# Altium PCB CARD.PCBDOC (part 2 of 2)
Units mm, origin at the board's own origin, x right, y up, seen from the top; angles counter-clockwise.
Board outline 129.79 x 109.73 mm, 2 copper layers (Top Layer, Bottom Layer); 204 components, 30 nets, 765 pads, 348 vias.
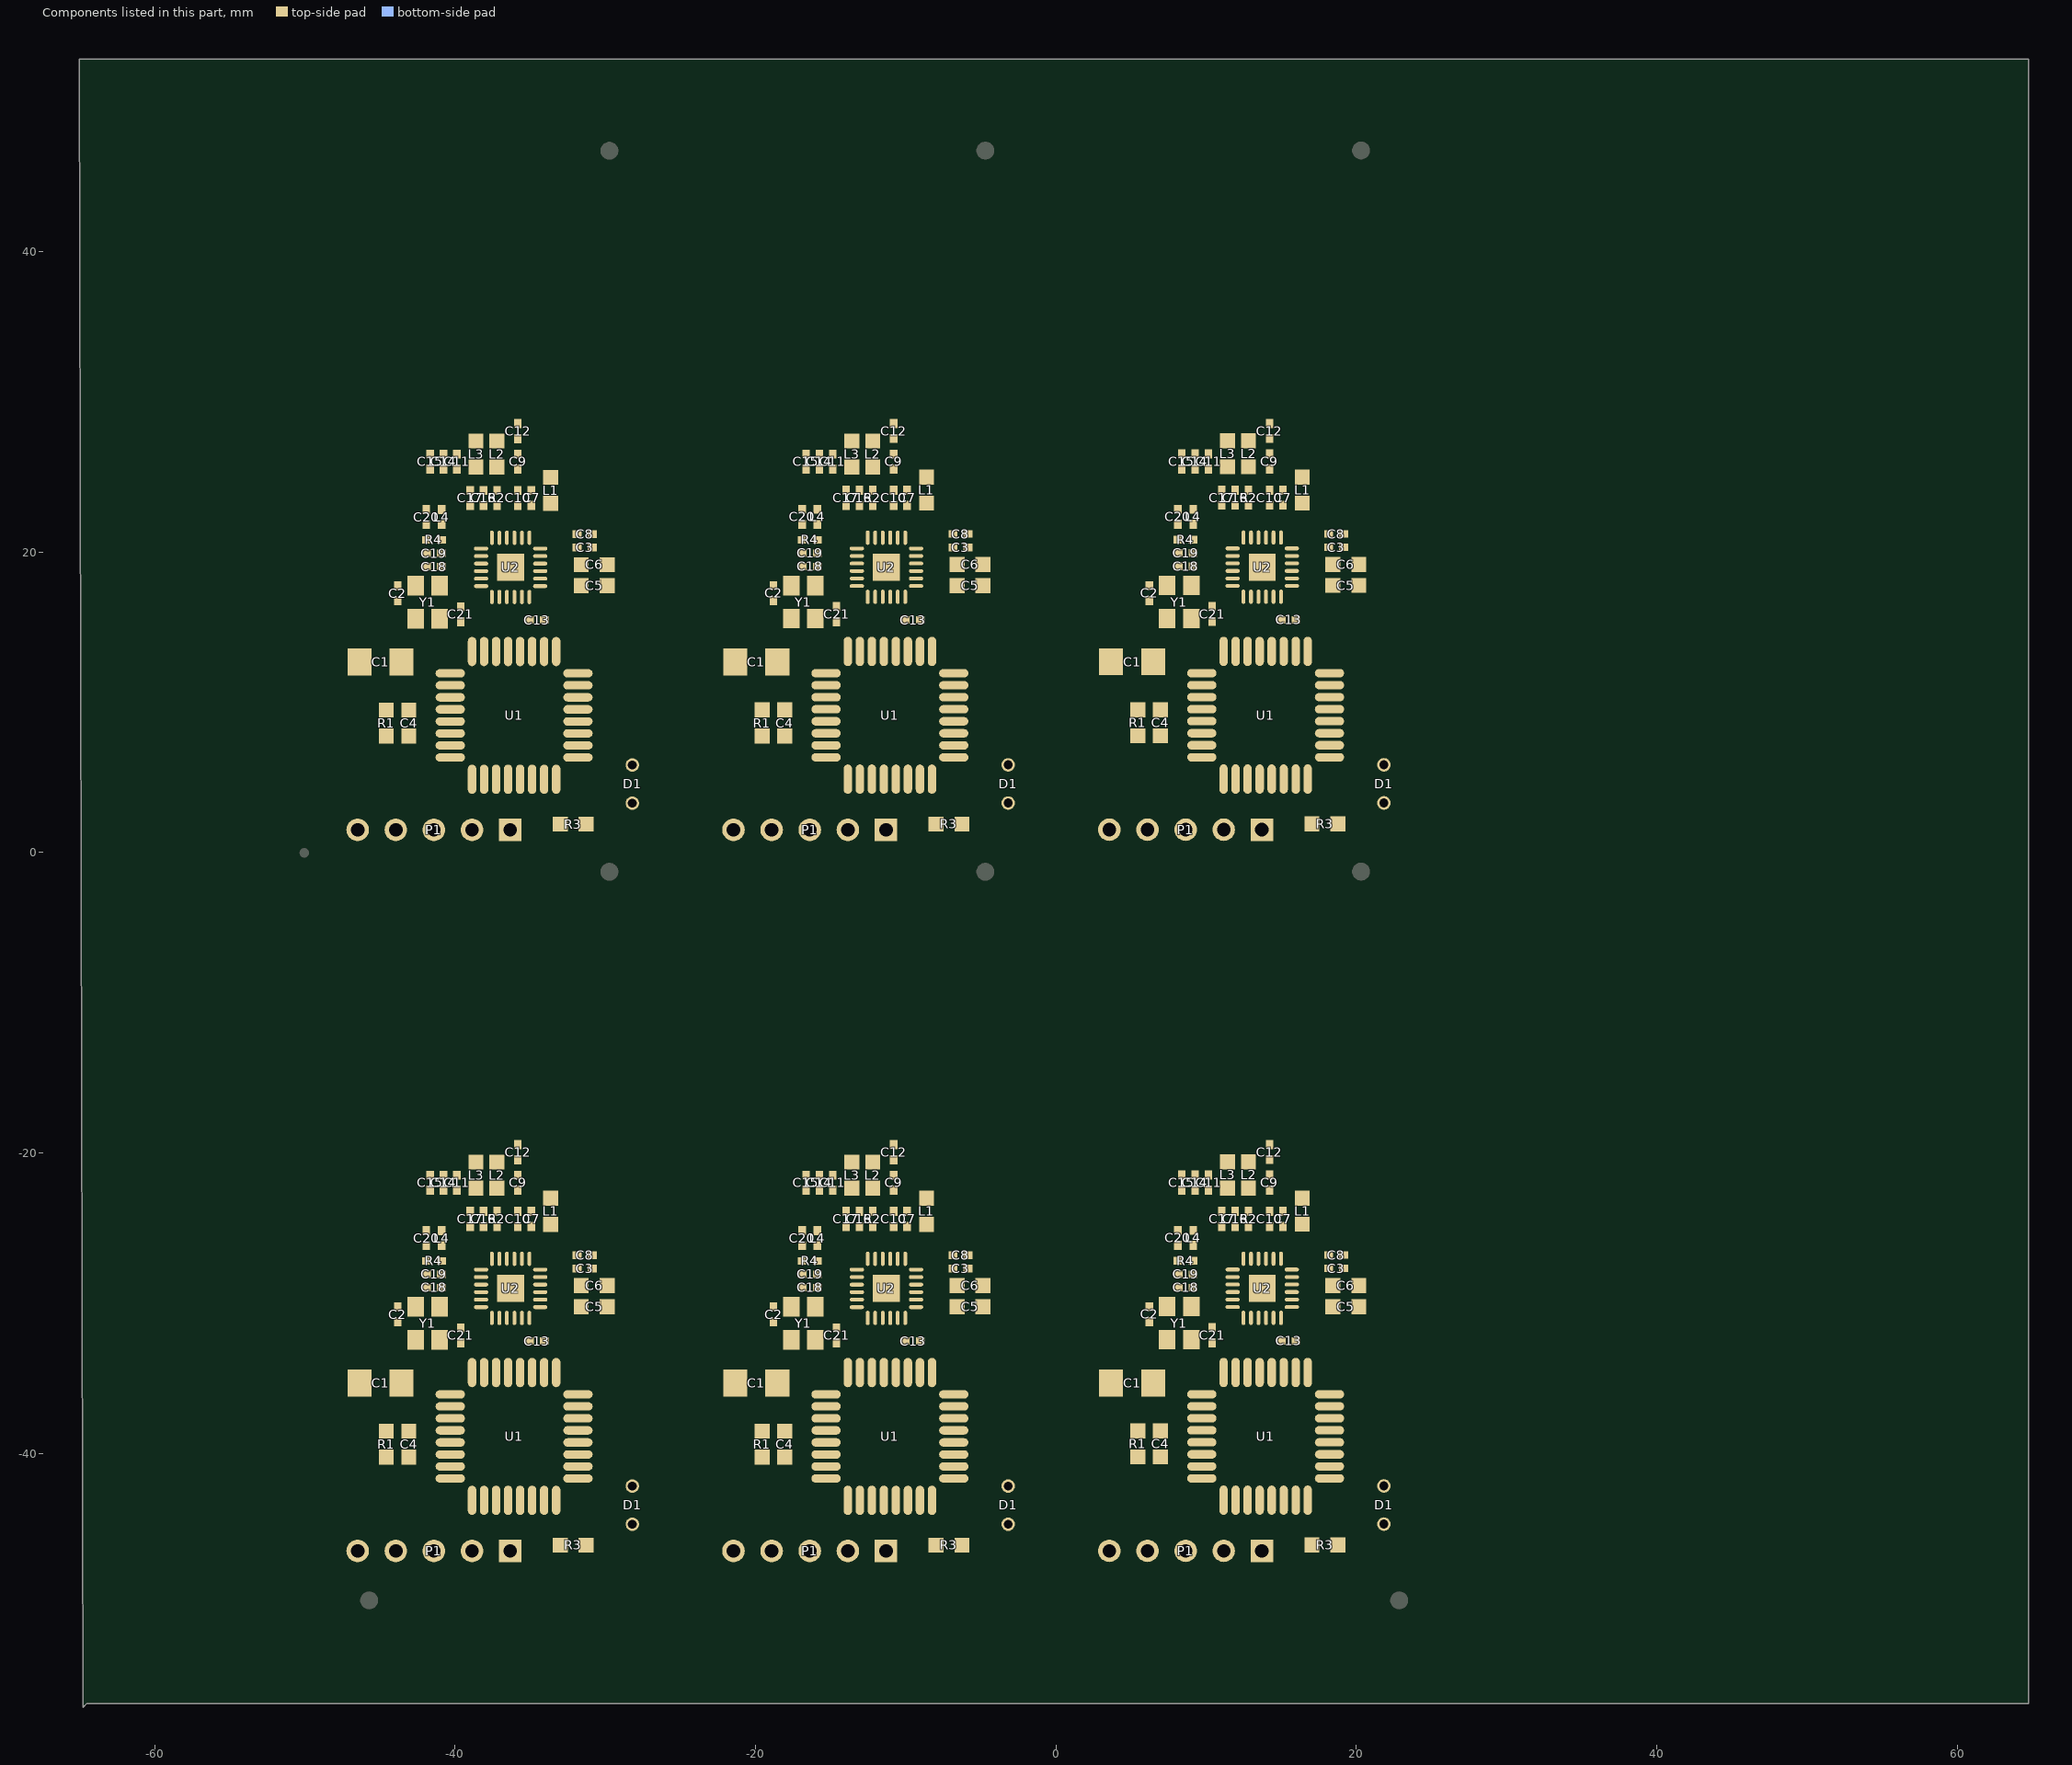
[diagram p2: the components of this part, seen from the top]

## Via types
v1: diameter 0.457, hole 0.381, Top Layer to Bottom Layer, 228 vias
v2: diameter 0.508, hole 0.305, Top Layer to Bottom Layer, 30 vias
v3: diameter 0.508, hole 0.254, Top Layer to Bottom Layer, tented top, 30 vias
v4: diameter 0.559, hole 0.356, Top Layer to Bottom Layer, 18 vias
v5: diameter 0.533, hole 0.279, Top Layer to Bottom Layer, 18 vias
v6: diameter 0.762, hole 0.457, Top Layer to Bottom Layer, 12 vias
v7: diameter 0.61, hole 0.356, Top Layer to Bottom Layer, 6 vias
v8: diameter 0.635, hole 0.381, Top Layer to Bottom Layer, 6 vias

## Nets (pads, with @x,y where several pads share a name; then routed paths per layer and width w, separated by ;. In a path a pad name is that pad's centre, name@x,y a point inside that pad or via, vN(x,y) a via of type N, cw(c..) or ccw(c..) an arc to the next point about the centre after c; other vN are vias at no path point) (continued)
copper on no net: | length 1969.2
  Top Layer w0.203: -43.942,-46.615 -43.028,-45.701 -43.028,-40.24 ; -43.942,1.385 -43.028,2.299 -43.028,7.76 ; -42.977,-44.837 -36.043,-44.837 -35.662,-44.456 -35.662,-43.745 ; -42.977,3.163 -36.043,3.163 -35.662,3.544 -35.662,4.255 ; -42.316,-30.715 -41.758,-31.273 -40.284,-31.273 -38.786,-29.775 -38.252,-29.775 ; -42.316,17.285 -41.758,16.727 -40.284,16.727 -38.786,18.225 -38.252,18.225 ; -40.894,-28.073 -40.767,-28.2 -40.386,-28.2 -39.827,-28.759 -38.456,-28.759 ; -40.894,19.927 -40.767,19.8 -40.386,19.8 -39.827,19.241 -38.456,19.241 ; -40.869,-26.27 -40.259,-26.27 cw(c-40.259,-26.676) -39.853,-26.676 -39.853,-27.895 ccw(c-39.497,-27.895) -39.497,-28.251 ; -40.869,21.73 -40.259,21.73 cw(c-40.259,21.324) -39.853,21.324 -39.853,20.105 ccw(c-39.497,20.105) -39.497,19.749 ; -40.767,-32.62 -38.608,-32.62 -38.456,-32.467 -38.456,-30.263 ; -40.767,15.38 -38.608,15.38 -38.456,15.533 -38.456,17.737 ; -40.742,-29.013 -40.361,-29.013 -40.107,-29.267 -38.075,-29.267 ; -40.742,18.987 -40.361,18.987 -40.107,18.733 -38.075,18.733 ; -40.691,-25.33 -39.903,-25.33 ; -40.691,22.67 -39.903,22.67 ; -40.081,-36.125 -39.091,-36.125 -38.608,-36.607 v2(-38.608,-41.484) ; -40.081,11.875 -39.091,11.875 -38.608,11.393 v2(-38.608,6.516) ; -39.929,-25.33 cw(c-39.929,-25.863) -39.395,-25.863 ; -39.929,22.67 cw(c-39.929,22.137) -39.395,22.137 ; -39.522,-28.251 -38.456,-28.251 ; -39.522,19.749 -38.456,19.749 ; -39.395,-25.838 -39.395,-27.387 ccw(c-39.014,-27.387) -39.014,-27.768 -38.303,-27.768 ; -39.395,22.162 -39.395,20.613 ccw(c-39.014,20.613) -39.014,20.232 -38.303,20.232 ; -38.76,-34.626 -38.76,-35.718 -37.973,-36.506 v2@-37.973,-41.154 ; -38.76,13.374 -38.76,12.282 -37.973,11.494 v2@-37.973,6.846 ; -37.998,-34.601 -37.998,-35.718 -37.338,-36.379 v2(-37.338,-40.9) ; -37.998,13.399 -37.998,12.282 -37.338,11.621 v2(-37.338,7.1) ; -37.965,-23.89 -37.236,-23.89 ; -37.965,24.11 -37.236,24.11 ; -37.268,-34.618 -37.268,-33.007 -37.059,-32.797 -37.059,-31.019 ; -37.268,13.382 -37.268,14.993 -37.059,15.203 -37.059,16.981 ; -37.211,-24.974 -37.211,-25.66 -37.059,-25.812 -37.059,-26.905 ; -37.211,-20.682 -37.211,-19.769 cw(c-36.777,-19.769) -37.084,-19.462 ; -37.211,23.026 -37.211,22.34 -37.059,22.188 -37.059,21.095 ; -37.211,27.318 -37.211,28.231 cw(c-36.777,28.231) -37.084,28.538 ; -37.059,-19.437 cw(c-36.767,-19.729) -36.767,-19.316 -35.973,-19.316 ; -37.059,28.563 cw(c-36.767,28.271) -36.767,28.684 -35.973,28.684 ; -36.957,-22.587 -36.551,-22.993 -36.551,-26.955 ; -36.957,25.413 -36.551,25.007 -36.551,21.045 ; -36.551,-34.067 -36.551,-31.146 ; -36.551,-27.108 -36.55,-27.043 -36.551,-27.082 ; -36.551,13.933 -36.551,16.854 ; -36.551,20.892 -36.55,20.957 -36.551,20.918 ; -36.047,-27.043 -36.047,-25.766 -35.814,-25.533 -35.814,-24.89 ; -36.047,20.957 -36.047,22.234 -35.814,22.467 -35.814,23.11 ; -36.043,-30.983 -36.043,-30.969 ; -36.043,-30.892 -36.043,-32.797 -35.662,-33.178 -35.662,-34.321 ; -36.043,17.017 -36.043,17.031 ; -36.043,17.108 -36.043,15.203 -35.662,14.822 -35.662,13.679 ; -35.839,-20.529 -35.814,-20.524 -35.798,-20.521 ; -35.839,27.471 -35.814,27.476 -35.798,27.479 ; -35.547,-30.983 -35.047,-30.983 -35.047,-32.338 ; -35.547,17.017 -35.047,17.017 -35.047,15.662 ; -35.047,-27.043 -35.047,-25.012 ; -35.047,20.957 -35.047,22.988 ; -34.442,-28.276 -33.426,-28.276 -32.918,-27.768 -32.004,-27.768 ; -34.442,19.724 -33.426,19.724 -32.918,20.232 -32.004,20.232 ; -34.327,-29.763 -33.362,-29.763 -33.198,-29.927 v2@-33.198,-31.197 ; -34.327,-27.763 -33.573,-27.763 -32.664,-26.854 -31.902,-26.854 ; -34.327,18.237 -33.362,18.237 -33.198,18.073 v2@-33.198,16.803 ; -34.327,20.237 -33.573,20.237 -32.664,21.146 -31.902,21.146 ; -34.087,-30.308 -34.087,-31.35 -33.655,-31.781 -32.614,-31.781 -29.769,-34.626 -29.769,-41.408 -30.023,-41.662 -31.217,-41.662 ; -34.087,17.692 -34.087,16.65 -33.655,16.219 -32.614,16.219 -29.769,13.374 -29.769,6.592 -30.023,6.338 -31.217,6.338 ; -33.198,-34.112 v2(-33.198,-32.366) ; -33.198,13.888 v2(-33.198,15.634) ; -18.923,-46.615 -18.009,-45.701 -18.009,-40.24 ; -18.923,1.391 -18.009,2.305 -18.009,7.766 ; -17.958,-44.837 -11.024,-44.837 -10.643,-44.456 -10.643,-43.745 ; -17.958,3.169 -11.024,3.169 -10.643,3.55 -10.643,4.261 ; -17.297,-30.715 -16.739,-31.273 -15.265,-31.273 -13.767,-29.775 -13.233,-29.775 ; -17.297,17.291 -16.739,16.733 -15.265,16.733 -13.767,18.231 -13.233,18.231 ; -15.875,-28.073 -15.748,-28.2 -15.367,-28.2 -14.808,-28.759 -13.437,-28.759 ; -15.875,19.933 -15.748,19.806 -15.367,19.806 -14.808,19.247 -13.437,19.247 ; -15.85,-26.27 -15.24,-26.27 cw(c-15.24,-26.676) -14.834,-26.676 -14.834,-27.895 ccw(c-14.478,-27.895) -14.478,-28.251 ; -15.85,21.736 -15.24,21.736 cw(c-15.24,21.33) -14.834,21.33 -14.834,20.111 ccw(c-14.478,20.111) -14.478,19.755 ; -15.748,-32.62 -13.589,-32.62 -13.437,-32.467 -13.437,-30.263 ; -15.748,15.386 -13.589,15.386 -13.437,15.539 -13.437,17.743 ; -15.723,-29.013 -15.342,-29.013 -15.088,-29.267 -13.056,-29.267 ; -15.723,18.993 -15.342,18.993 -15.088,18.739 -13.056,18.739 ; -15.672,-25.33 -14.884,-25.33 ; -15.672,22.676 -14.884,22.676 ; -15.062,-36.125 -14.072,-36.125 -13.589,-36.607 v2(-13.589,-41.484) ; -15.062,11.881 -14.072,11.881 -13.589,11.399 v2(-13.589,6.522) ; -14.91,-25.33 cw(c-14.91,-25.863) -14.376,-25.863 ; -14.91,22.676 cw(c-14.91,22.143) -14.376,22.143 ; -14.503,-28.251 -13.437,-28.251 ; -14.503,19.755 -13.437,19.755 ; -14.376,-25.838 -14.376,-27.387 ccw(c-13.995,-27.387) -13.995,-27.768 -13.284,-27.768 ; -14.376,22.168 -14.376,20.619 ccw(c-13.995,20.619) -13.995,20.238 -13.284,20.238 ; -13.741,-34.626 -13.741,-35.718 -12.954,-36.506 v2@-12.954,-41.154 ; -13.741,13.38 -13.741,12.288 -12.954,11.5 v2@-12.954,6.852 ; -12.979,-34.601 -12.979,-35.718 -12.319,-36.379 v2(-12.319,-40.9) ; -12.979,13.405 -12.979,12.288 -12.319,11.627 v2(-12.319,7.106) ; -12.946,-23.89 -12.217,-23.89 ; -12.946,24.116 -12.217,24.116 ; -12.249,-34.618 -12.249,-33.007 -12.04,-32.797 -12.04,-31.019 ; -12.249,13.388 -12.249,14.999 -12.04,15.209 -12.04,16.987 ; -12.192,-24.974 -12.192,-25.66 -12.04,-25.812 -12.04,-26.905 ; -12.192,-20.682 -12.192,-19.769 cw(c-11.758,-19.769) -12.065,-19.462 ; -12.192,23.032 -12.192,22.346 -12.04,22.194 -12.04,21.101 ; -12.192,27.324 -12.192,28.237 cw(c-11.758,28.237) -12.065,28.544 ; -12.04,-19.437 cw(c-11.748,-19.729) -11.748,-19.316 -10.954,-19.316 ; -12.04,28.569 cw(c-11.748,28.277) -11.748,28.69 -10.954,28.69 ; -11.938,-22.587 -11.532,-22.993 -11.532,-26.955 ; -11.938,25.419 -11.532,25.013 -11.532,21.051 ; -11.532,-34.067 -11.532,-31.146 ; -11.532,-27.108 -11.531,-27.043 -11.532,-27.082 ; -11.532,13.939 -11.532,16.86 ; -11.532,20.898 -11.531,20.963 -11.532,20.924 ; -11.028,-27.043 -11.028,-25.766 -10.795,-25.533 -10.795,-24.89 ; -11.028,20.963 -11.028,22.24 -10.795,22.473 -10.795,23.116 ; -11.024,-30.983 -11.024,-30.969 ; -11.024,-30.892 -11.024,-32.797 -10.643,-33.178 -10.643,-34.321 ; -11.024,17.023 -11.024,17.037 ; -11.024,17.114 -11.024,15.209 -10.643,14.828 -10.643,13.685 ; -10.82,-20.529 -10.795,-20.524 -10.779,-20.521 ; -10.82,27.477 -10.795,27.482 -10.779,27.485 ; -10.528,-30.983 -10.028,-30.983 -10.028,-32.338 ; -10.528,17.023 -10.028,17.023 -10.028,15.668 ; -10.028,-27.043 -10.028,-25.012 ; -10.028,20.963 -10.028,22.994 ; -9.423,-28.276 -8.407,-28.276 -7.899,-27.768 -6.985,-27.768 ; -9.423,19.73 -8.407,19.73 -7.899,20.238 -6.985,20.238 ; -9.308,-29.763 -8.343,-29.763 -8.179,-29.927 v2@-8.179,-31.197 ; -9.308,-27.763 -8.554,-27.763 -7.645,-26.854 -6.883,-26.854 ; -9.308,18.243 -8.343,18.243 -8.179,18.079 v2@-8.179,16.809 ; -9.308,20.243 -8.554,20.243 -7.645,21.152 -6.883,21.152 ; -9.068,-30.308 -9.068,-31.35 -8.636,-31.781 -7.595,-31.781 -4.75,-34.626 -4.75,-41.408 -5.004,-41.662 -6.198,-41.662 ; -9.068,17.698 -9.068,16.656 -8.636,16.225 -7.595,16.225 -4.75,13.38 -4.75,6.598 -5.004,6.344 -6.198,6.344 ; -8.179,-34.112 v2(-8.179,-32.366) ; -8.179,13.894 v2(-8.179,15.64) ; 6.096,-46.609 7.01,-45.695 7.01,-40.234 ; 7.061,-44.831 13.995,-44.831 14.376,-44.45 14.376,-43.739 ; 7.722,-30.709 8.28,-31.267 9.754,-31.267 11.252,-29.769 11.786,-29.769 ; 9.144,-28.067 9.271,-28.194 9.652,-28.194 10.211,-28.753 11.582,-28.753 ; 9.169,-26.264 9.779,-26.264 cw(c9.779,-26.67) 10.185,-26.67 10.185,-27.889 ccw(c10.541,-27.889) 10.541,-28.245 ; 9.271,-32.614 11.43,-32.614 11.582,-32.461 11.582,-30.257 ; 9.296,-29.007 9.677,-29.007 9.931,-29.261 11.963,-29.261 ; 9.347,-25.324 10.135,-25.324 ; 9.957,-36.119 10.947,-36.119 11.43,-36.601 v2(11.43,-41.478) ; 10.109,-25.324 cw(c10.109,-25.857) 10.643,-25.857 ; 10.516,-28.245 11.582,-28.245 ; 10.643,-25.832 10.643,-27.381 ccw(c11.024,-27.381) 11.024,-27.762 11.735,-27.762 ; 11.278,-34.62 11.278,-35.712 12.065,-36.5 v2@12.065,-41.148 ; 12.04,-34.595 12.04,-35.712 12.7,-36.373 v2(12.7,-40.894) ; 12.073,-23.884 12.802,-23.884 ; 12.77,-34.612 12.77,-33.001 12.979,-32.791 12.979,-31.013 ; 12.827,-24.968 12.827,-25.654 12.979,-25.806 12.979,-26.899 ; 12.827,-20.676 12.827,-19.763 cw(c13.261,-19.763) 12.954,-19.456 ; 12.979,-19.431 cw(c13.271,-19.723) 13.271,-19.31 14.065,-19.31 ; 13.081,-22.581 13.487,-22.987 13.487,-26.949 ; 13.487,-34.061 13.487,-31.14 ; 13.487,-27.102 13.488,-27.037 13.487,-27.076 ; 13.991,-27.037 13.991,-25.76 14.224,-25.527 14.224,-24.884 ; 13.995,-30.977 13.995,-30.963 ; 13.995,-30.886 13.995,-32.791 14.376,-33.172 14.376,-34.315 ; 14.199,-20.523 14.224,-20.518 14.24,-20.515 ; 14.491,-30.977 14.991,-30.977 14.991,-32.332 ; 14.991,-27.037 14.991,-25.006 ; 15.596,-28.27 16.612,-28.27 17.12,-27.762 18.034,-27.762 ; 15.711,-29.757 16.676,-29.757 16.84,-29.921 v2@16.84,-31.191 ; 15.711,-27.757 16.465,-27.757 17.374,-26.848 18.136,-26.848 ; 15.951,-30.302 15.951,-31.344 16.383,-31.775 17.424,-31.775 20.269,-34.62 20.269,-41.402 20.015,-41.656 18.821,-41.656 ; 16.84,-34.106 v2(16.84,-32.36)
  Top Layer w0.254: -44.577,-40.24 -43.078,-40.24 ; -44.577,7.76 -43.078,7.76 ; -39.802,-21.571 -39.395,-21.571 -38.946,-22.02 ; -39.802,26.429 -39.395,26.429 -38.946,25.98 ; -39.395,-31.654 v4@-39.167,-31.654 ; -39.395,16.346 v4@-39.167,16.346 ; -35.547,-28.263 -35.547,-27.159 ; -35.547,19.737 -35.547,20.841 ; v4@-34.036,-33.004 -34.036,-32.645 ; v4@-34.036,14.996 -34.036,15.355 ; -19.558,-40.24 -18.059,-40.24 ; -19.558,7.766 -18.059,7.766 ; -14.783,-21.571 -14.376,-21.571 -13.927,-22.02 ; -14.783,26.435 -14.376,26.435 -13.927,25.986 ; -14.376,-31.654 v4@-14.148,-31.654 ; -14.376,16.352 v4@-14.148,16.352 ; -10.528,-28.263 -10.528,-27.159 ; -10.528,19.743 -10.528,20.847 ; v4@-9.017,-33.004 -9.017,-32.645 ; v4@-9.017,15.002 -9.017,15.361 ; 5.461,-40.234 6.96,-40.234 ; 10.236,-21.565 10.643,-21.565 11.092,-22.014 ; 10.643,-31.648 v4@10.871,-31.648 ; 14.491,-28.257 14.491,-27.153 ; v4@16.002,-32.998 16.002,-32.639
  Top Layer w0.305: -43.764,-30.232 -42.807,-30.232 ; -43.764,17.768 -42.807,17.768 ; -41.91,-27.26 -41.91,-26.168 ; -41.91,20.74 -41.91,21.832 ; -41.681,-21.494 -41.656,-21.469 -41.656,-19.437 ; -41.681,-21.469 -40.716,-21.469 ; -41.681,26.506 -41.656,26.531 -41.656,28.563 ; -41.681,26.531 -40.716,26.531 ; -40.894,-27.878 -40.894,-27.311 ; -40.894,20.122 -40.894,20.689 ; -38.887,-24.992 -38.887,-26.473 -38.557,-26.803 -37.592,-26.803 ; -38.887,23.008 -38.887,21.527 -38.557,21.197 -37.592,21.197 ; -38.837,-22.46 -37.287,-22.46 ; -38.837,25.54 -37.287,25.54 ; v4@-37.567,-31.985 -37.567,-31.29 ; v4@-37.567,16.015 -37.567,16.71 ; -35.814,-23.89 -35.814,-22.46 ; -35.814,24.11 -35.814,25.54 ; -35.763,-22.993 -33.63,-22.993 ; -35.763,25.007 -33.63,25.007 ; -34.925,-23.89 -34.485,-23.89 -34.011,-24.365 ; -34.925,24.11 -34.485,24.11 -34.011,23.635 ; -34.327,-28.763 -31.598,-28.763 ; -34.327,19.237 -31.598,19.237 ; -32.309,-39.274 -33.426,-39.274 -33.757,-38.944 -33.757,-37.928 -33.477,-37.649 -32.283,-37.649 ; -32.309,8.726 -33.426,8.726 -33.757,9.056 -33.757,10.072 -33.477,10.351 -32.283,10.351 ; -31.623,-28.835 -31.623,-31.756 -29.058,-34.321 v8@-29.058,-37.598 ; -31.623,19.165 -31.623,16.244 -29.058,13.679 v8@-29.058,10.402 ; -18.745,-30.232 -17.788,-30.232 ; -18.745,17.774 -17.788,17.774 ; -16.891,-27.26 -16.891,-26.168 ; -16.891,20.746 -16.891,21.838 ; -16.662,-21.494 -16.637,-21.469 -16.637,-19.437 ; -16.662,-21.469 -15.697,-21.469 ; -16.662,26.512 -16.637,26.537 -16.637,28.569 ; -16.662,26.537 -15.697,26.537 ; -15.875,-27.878 -15.875,-27.311 ; -15.875,20.128 -15.875,20.695 ; -13.868,-24.992 -13.868,-26.473 -13.538,-26.803 -12.573,-26.803 ; -13.868,23.014 -13.868,21.533 -13.538,21.203 -12.573,21.203 ; -13.818,-22.46 -12.268,-22.46 ; -13.818,25.546 -12.268,25.546 ; v4@-12.548,-31.985 -12.548,-31.29 ; v4@-12.548,16.021 -12.548,16.716 ; -10.795,-23.89 -10.795,-22.46 ; -10.795,24.116 -10.795,25.546 ; -10.744,-22.993 -8.611,-22.993 ; -10.744,25.013 -8.611,25.013 ; -9.906,-23.89 -9.466,-23.89 -8.992,-24.365 ; -9.906,24.116 -9.466,24.116 -8.992,23.641 ; -9.308,-28.763 -6.579,-28.763 ; -9.308,19.243 -6.579,19.243 ; -7.29,-39.274 -8.407,-39.274 -8.738,-38.944 -8.738,-37.928 -8.458,-37.649 -7.264,-37.649 ; -7.29,8.732 -8.407,8.732 -8.738,9.062 -8.738,10.078 -8.458,10.357 -7.264,10.357 ; -6.604,-28.835 -6.604,-31.756 -4.039,-34.321 v8@-4.039,-37.598 ; -6.604,19.171 -6.604,16.25 -4.039,13.685 v8@-4.039,10.408 ; 6.274,-30.226 7.231,-30.226 ; 8.128,-27.254 8.128,-26.162 ; 8.357,-21.488 8.382,-21.463 8.382,-19.431 ; 8.357,-21.463 9.322,-21.463 ; 9.144,-27.872 9.144,-27.305 ; 11.151,-24.986 11.151,-26.467 11.481,-26.797 12.446,-26.797 ; 11.201,-22.454 12.751,-22.454 ; v4@12.471,-31.979 12.471,-31.284 ; 14.224,-23.884 14.224,-22.454 ; 14.275,-22.987 16.408,-22.987 ; 15.113,-23.884 15.553,-23.884 16.027,-24.359 ; 15.711,-28.757 18.44,-28.757 ; 17.729,-39.268 16.612,-39.268 16.281,-38.938 16.281,-37.922 16.561,-37.643 17.755,-37.643 ; 18.415,-28.829 18.415,-31.75 20.98,-34.315 v8@20.98,-37.592
  Top Layer w0.33: -35.798,-21.468 -35.798,-20.521 ; -35.798,26.532 -35.798,27.479 ; -35.756,-20.453 -35.746,-20.377 ; -35.756,27.547 -35.746,27.623 ; -10.779,-21.468 -10.779,-20.521 ; -10.779,26.538 -10.779,27.485 ; -10.737,-20.453 -10.727,-20.377 ; -10.737,27.553 -10.727,27.629 ; 14.24,-21.462 14.24,-20.515 ; 14.282,-20.447 14.292,-20.371
  Top Layer w0.381: v7@-38.1,-25.558 -38.1,-24.89 ; v7@-38.1,22.442 -38.1,23.11 ; v6@-34.62,-38.436 -33.833,-38.436 ; v6@-34.62,9.564 -33.833,9.564 ; -33.274,-45.98 -33.274,-43.694 ; -33.274,-43.118 -33.274,-43.059 ; -33.274,2.02 -33.274,4.306 ; -33.274,4.882 -33.274,4.941 ; -31.818,-40.068 -30.537,-40.068 -30.353,-39.884 -30.353,-38.614 -30.499,-38.468 -31.818,-38.468 ; -31.818,7.932 -30.537,7.932 -30.353,8.116 -30.353,9.386 -30.499,9.532 -31.818,9.532 ; -31.242,-46.107 -29.591,-46.107 -28.194,-44.71 ; -31.242,1.893 -29.591,1.893 -28.194,3.29 ; v7@-13.081,-25.558 -13.081,-24.89 ; v7@-13.081,22.448 -13.081,23.116 ; v6@-9.601,-38.436 -8.814,-38.436 ; v6@-9.601,9.57 -8.814,9.57 ; -8.255,-45.98 -8.255,-43.694 ; -8.255,-43.118 -8.255,-43.059 ; -8.255,2.026 -8.255,4.312 ; -8.255,4.888 -8.255,4.947 ; -6.799,-40.068 -5.518,-40.068 -5.334,-39.884 -5.334,-38.614 -5.48,-38.468 -6.799,-38.468 ; -6.799,7.938 -5.518,7.938 -5.334,8.122 -5.334,9.392 -5.48,9.538 -6.799,9.538 ; -6.223,-46.107 -4.572,-46.107 -3.175,-44.71 ; -6.223,1.899 -4.572,1.899 -3.175,3.296 ; v7@11.938,-25.552 11.938,-24.884 ; v6@15.418,-38.43 16.205,-38.43 ; 16.764,-45.974 16.764,-43.688 ; 16.764,-43.112 16.764,-43.053 ; 18.22,-40.062 19.501,-40.062 19.685,-39.878 19.685,-38.608 19.539,-38.462 18.22,-38.462 ; 18.796,-46.101 20.447,-46.101 21.844,-44.704
  Top Layer w0.406: v6@-45.593,-38.411 -44.679,-38.411 ; v6@-45.593,9.589 -44.679,9.589 ; v6@-20.574,-38.411 -19.66,-38.411 ; v6@-20.574,9.595 -19.66,9.595 ; v6@4.445,-38.405 5.359,-38.405
  Top Layer w0.508: -46.228,-35.058 -46.228,-20.58 -45.085,-19.437 -38.887,-19.437 -38.608,-19.716 -38.608,-20.605 ; -46.228,12.942 -46.228,27.42 -45.085,28.563 -38.887,28.563 -38.608,28.284 -38.608,27.395 ; -46.025,-35.464 -46.025,-37.979 v6@-45.593,-38.411 ; -46.025,12.536 -46.025,10.021 v6@-45.593,9.589 ; -21.209,-35.058 -21.209,-20.58 -20.066,-19.437 -13.868,-19.437 -13.589,-19.716 -13.589,-20.605 ; -21.209,12.948 -21.209,27.426 -20.066,28.569 -13.868,28.569 -13.589,28.29 -13.589,27.401 ; -21.006,-35.464 -21.006,-37.979 v6@-20.574,-38.411 ; -21.006,12.542 -21.006,10.027 v6@-20.574,9.595 ; 3.81,-35.052 3.81,-20.574 4.953,-19.431 11.151,-19.431 11.43,-19.71 11.43,-20.599 ; 4.013,-35.458 4.013,-37.973 v6@4.445,-38.405
  Top Layer w1.016: -48.184,-35.414 -46.965,-35.414 ; -48.184,12.586 -46.965,12.586 ; -23.165,-35.414 -21.946,-35.414 ; -23.165,12.592 -21.946,12.592 ; 1.854,-35.408 3.073,-35.408
  Top Layer w1.15: -47.739,-17.99 -27.445,-17.99 cw(c-27.382,-19.488) -27.457,-20.986 -35.481,-20.986 ; -47.739,-17.989 cw(c-47.802,-16.49) -47.727,-14.992 -27.697,-14.992 ; -47.739,30.01 -27.445,30.01 cw(c-27.382,28.512) -27.457,27.014 -35.481,27.014 ; -47.739,30.011 cw(c-47.802,31.51) -47.727,33.008 -27.697,33.008 ; -47.65,-6.002 -27.699,-6.002 cw(c-27.636,-7.5) -27.712,-8.998 -47.523,-8.998 ccw(c-47.599,-10.497) -47.536,-11.995 -27.724,-11.995 cw(c-27.661,-13.494) -27.737,-14.992 ; -47.65,-3.005 -25.781,-3.005 ; -47.65,41.998 -27.699,41.998 cw(c-27.636,40.5) -27.712,39.002 -47.523,39.002 ccw(c-47.599,37.503) -47.536,36.005 -27.724,36.005 cw(c-27.661,34.506) -27.737,33.008 ; -47.65,44.995 -25.781,44.995 ; -47.574,-6 cw(c-47.637,-4.502) -47.562,-3.004 ; -47.574,42 cw(c-47.637,43.498) -47.562,44.996 ; -22.72,-17.99 -2.426,-17.99 cw(c-2.363,-19.488) -2.438,-20.986 -10.462,-20.986 ; -22.72,-17.989 cw(c-22.783,-16.49) -22.708,-14.992 -2.678,-14.992 ; -22.72,30.016 -2.426,30.016 cw(c-2.363,28.518) -2.438,27.02 -10.462,27.02 ; -22.72,30.017 cw(c-22.783,31.516) -22.708,33.014 -2.678,33.014 ; -22.631,-6.002 -2.68,-6.002 cw(c-2.617,-7.5) -2.693,-8.998 -22.504,-8.998 ccw(c-22.58,-10.497) -22.517,-11.995 -2.705,-11.995 cw(c-2.642,-13.494) -2.718,-14.992 ; -22.631,-3.005 -0.762,-3.005 ; -22.631,42.004 -2.68,42.004 cw(c-2.617,40.506) -2.693,39.008 -22.504,39.008 ccw(c-22.58,37.509) -22.517,36.011 -2.705,36.011 cw(c-2.642,34.512) -2.718,33.014 ; -22.631,45.001 -0.762,45.001 ; -22.555,-6 cw(c-22.618,-4.502) -22.543,-3.004 ; -22.555,42.006 cw(c-22.618,43.504) -22.543,45.002 ; 2.388,-5.996 22.339,-5.996 cw(c22.402,-7.494) 22.326,-8.992 2.515,-8.992 ccw(c2.439,-10.491) 2.502,-11.989 22.314,-11.989 cw(c22.377,-13.488) 22.301,-14.986 ; 2.388,-2.999 24.257,-2.999 ; 2.464,-5.994 cw(c2.401,-4.496) 2.476,-2.998 ; 14.557,-20.98 22.581,-20.98 ccw(c22.656,-19.482) 22.593,-17.984 2.299,-17.984 cw(c2.236,-16.484) 2.311,-14.986 22.341,-14.986
  Bottom Layer w0.203: -41.25,-46.463 -40.564,-46.463 -38.633,-44.532 v2@-38.633,-41.484 ; -41.25,1.537 -40.564,1.537 -38.633,3.468 v2@-38.633,6.516 ; -38.862,-46.615 -38.862,-46.463 -37.973,-45.574 v2(-37.973,-41.205) ; -38.862,1.385 -38.862,1.537 -37.973,2.426 v2(-37.973,6.795) ; v2(-37.338,-40.9) -37.338,-45.497 -36.398,-46.437 -36.398,-46.539 ; v2(-37.338,7.1) -37.338,2.503 -36.398,1.563 -36.398,1.461 ; v2@-33.198,-32.289 v2@-33.198,-31.07 ; v2@-33.198,15.711 v2@-33.198,16.93 ; -16.231,-46.463 -15.545,-46.463 -13.614,-44.532 v2@-13.614,-41.484 ; -16.231,1.543 -15.545,1.543 -13.614,3.474 v2@-13.614,6.522 ; -13.843,-46.615 -13.843,-46.463 -12.954,-45.574 v2(-12.954,-41.205) ; -13.843,1.391 -13.843,1.543 -12.954,2.432 v2(-12.954,6.801) ; v2(-12.319,-40.9) -12.319,-45.497 -11.379,-46.437 -11.379,-46.539 ; v2(-12.319,7.106) -12.319,2.509 -11.379,1.569 -11.379,1.467 ; v2@-8.179,-32.289 v2@-8.179,-31.07 ; v2@-8.179,15.717 v2@-8.179,16.936 ; 8.788,-46.457 9.474,-46.457 11.405,-44.526 v2@11.405,-41.478 ; 11.176,-46.609 11.176,-46.457 12.065,-45.568 v2(12.065,-41.199) ; v2(12.7,-40.894) 12.7,-45.491 13.64,-46.431 13.64,-46.533 ; v2@16.84,-32.283 v2@16.84,-31.064
  Bottom Layer w0.305: v5(-39.573,-29.343) -40.132,-28.784 -40.132,-26.93 -39.853,-26.651 -32.969,-26.651 -32.639,-26.981 v5(-32.639,-27.768) ; v5(-39.573,18.657) -40.132,19.216 -40.132,21.07 -39.853,21.349 -32.969,21.349 -32.639,21.019 v5(-32.639,20.232) ; v5(-14.554,-29.343) -15.113,-28.784 -15.113,-26.93 -14.834,-26.651 -7.95,-26.651 -7.62,-26.981 v5(-7.62,-27.768) ; v5(-14.554,18.663) -15.113,19.222 -15.113,21.076 -14.834,21.355 -7.95,21.355 -7.62,21.025 v5(-7.62,20.238) ; v5(10.465,-29.337) 9.906,-28.778 9.906,-26.924 10.185,-26.645 17.069,-26.645 17.399,-26.975 v5(17.399,-27.762)
  Bottom Layer w0.508: -34.265,-38.436 -33.426,-37.598 v8@-29.032,-37.598 ; -34.265,9.564 -33.426,10.402 v8@-29.032,10.402 ; -9.246,-38.436 -8.407,-37.598 v8@-4.013,-37.598 ; -9.246,9.57 -8.407,10.408 v8@-4.013,10.408 ; 15.773,-38.43 16.612,-37.592 v8@21.006,-37.592
  Bottom Layer w0.635: v6@-45.568,-38.436 -34.265,-38.436 ; v6@-45.568,9.564 -34.265,9.564 ; v6@-20.549,-38.436 -9.246,-38.436 ; v6@-20.549,9.57 -9.246,9.57 ; v6@4.47,-38.43 15.773,-38.43
  other v1: -33.147,-47.25 -31.623,-47.25 -8.128,-47.25 -6.604,-47.25 16.891,-47.244 18.415,-47.244 -28.575,-46.996 -3.556,-46.996 21.463,-46.99 -34.671,-44.964 -34.163,-44.964 -26.035,-44.964 -9.652,-44.964 -9.144,-44.964 -1.016,-44.964 15.367,-44.958 15.875,-44.958 24.003,-44.958 -26.035,-44.456 -1.016,-44.456 24.003,-44.45 -31.623,-43.186 -31.115,-43.186 -6.604,-43.186 -6.096,-43.186 18.415,-43.18 18.923,-43.18 -48.133,-42.932 -47.625,-42.932 -47.117,-42.932 -41.275,-42.932 -40.767,-42.932 -40.259,-42.932 -23.114,-42.932 -22.606,-42.932 -22.098,-42.932 -16.256,-42.932 -15.748,-42.932 -15.24,-42.932 1.905,-42.926 2.413,-42.926 2.921,-42.926 8.763,-42.926 9.271,-42.926 9.779,-42.926 -35.433,-41.154 -10.414,-41.154 14.605,-41.148 -35.433,-40.392 -10.414,-40.392 14.605,-40.386 -27.813,-37.852 -27.305,-37.852 -26.797,-37.852 -2.794,-37.852 -2.286,-37.852 -1.778,-37.852 22.225,-37.846 22.733,-37.846 23.241,-37.846 -35.941,-36.836 -35.179,-36.836 -10.922,-36.836 -10.16,-36.836 14.097,-36.83 14.859,-36.83 -41.783,-34.296 -41.275,-34.296 -40.767,-34.296 -16.764,-34.296 -16.256,-34.296 -15.748,-34.296 8.255,-34.29 8.763,-34.29 9.271,-34.29 -47.879,-30.232 -22.86,-30.232 2.159,-30.226 -47.879,-29.724 -22.86,-29.724 2.159,-29.718 -47.879,-29.216 -22.86,-29.216 2.159,-29.21 -44.323,-28.2 -43.815,-28.2 -19.304,-28.2 -18.796,-28.2 5.715,-28.194 6.223,-28.194 -27.813,-26.676 -2.794,-26.676 22.225,-26.67 -27.813,-26.168 -2.794,-26.168 22.225,-26.162 -27.813,-25.66 -2.794,-25.66 22.225,-25.654 -27.813,-25.152 -2.794,-25.152 22.225,-25.146 -40.005,-23.882 -14.986,-23.882 10.033,-23.876 -44.577,-22.612 -44.069,-22.612 -43.561,-22.612 -19.558,-22.612 -19.05,-22.612 -18.542,-22.612 5.461,-22.606 5.969,-22.606 6.477,-22.606 -33.147,0.75 -31.623,0.75 -8.128,0.756 -6.604,0.756 -28.575,1.004 -3.556,1.01 -34.671,3.036 -34.163,3.036 -26.035,3.036 -9.652,3.042 -9.144,3.042 -1.016,3.042 -26.035,3.544 -1.016,3.55 -31.623,4.814 -31.115,4.814 -6.604,4.82 -6.096,4.82 -48.133,5.068 -47.625,5.068 -47.117,5.068 -41.275,5.068 -40.767,5.068 -40.259,5.068 -23.114,5.074 -22.606,5.074 -22.098,5.074 -16.256,5.074 -15.748,5.074 -15.24,5.074 -35.433,6.846 -10.414,6.852 -35.433,7.608 -10.414,7.614 -27.813,10.148 -27.305,10.148 -26.797,10.148 -2.794,10.154 -2.286,10.154 -1.778,10.154 -35.941,11.164 -35.179,11.164 -10.922,11.17 -10.16,11.17 -41.783,13.704 -41.275,13.704 -40.767,13.704 -16.764,13.71 -16.256,13.71 -15.748,13.71 -47.879,17.768 -22.86,17.774 -47.879,18.276 -22.86,18.282 -47.879,18.784 -22.86,18.79 -44.323,19.8 -43.815,19.8 -19.304,19.806 -18.796,19.806 -27.813,21.324 -2.794,21.33 -27.813,21.832 -2.794,21.838 -27.813,22.34 -2.794,22.346 -27.813,22.848 -2.794,22.854 -40.005,24.118 -14.986,24.124 -44.577,25.388 -44.069,25.388 -43.561,25.388 -19.558,25.394 -19.05,25.394 -18.542,25.394
  other v2: -33.172,-31.172 -8.153,-31.172 16.866,-31.166 -33.172,16.828 -8.153,16.834
  other v3: -36.847,-29.563 -35.747,-29.563 -11.828,-29.563 -10.728,-29.563 13.191,-29.557 14.291,-29.557 -36.297,-29.013 -11.278,-29.013 13.741,-29.007 -36.847,-28.463 -35.747,-28.463 -11.828,-28.463 -10.728,-28.463 13.191,-28.457 14.291,-28.457 -36.847,18.437 -35.747,18.437 -11.828,18.443 -10.728,18.443 -36.297,18.987 -11.278,18.993 -36.847,19.537 -35.747,19.537 -11.828,19.543 -10.728,19.543
  other v4: -34.036,-33.026 -9.017,-33.026 16.002,-33.02 -37.592,-32.01 -12.573,-32.01 12.446,-32.004 -39.116,-31.629 -14.097,-31.629 10.922,-31.623 -34.036,14.974 -9.017,14.98 -37.592,15.99 -12.573,15.996 -39.116,16.371 -14.097,16.377
  other v5: -38.71,-26.651 -13.691,-26.651 11.328,-26.645 -38.71,21.349 -13.691,21.355
  other v6: -34.646,-38.462 -9.627,-38.462 15.392,-38.456 -45.593,-38.436 -20.574,-38.436 4.445,-38.43 -34.646,9.538 -9.627,9.544 -45.593,9.564 -20.574,9.57
  other v7: -38.1,-25.66 -13.081,-25.66 11.938,-25.654 -38.1,22.34 -13.081,22.346
  other v8: -29.032,-37.623 -4.013,-37.623 21.006,-37.617 -29.032,10.377 -4.013,10.383

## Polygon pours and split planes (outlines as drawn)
no net on Top Layer "Bottom Layer-No Net" (solid, remove dead copper, pour order 1005): -50.546,28.817 -23.622,28.817 -23.622,-2.044 -23.876,-2.298 -25.019,-1.155 -51.054,-1.155
no net on Top Layer "Bottom Layer-No Net" (solid, remove dead copper, pour order 1004): -50.546,-19.183 -23.622,-19.183 -23.622,-50.044 -23.876,-50.298 -25.019,-49.155 -51.054,-49.155
no net on Top Layer "Bottom Layer-No Net" (solid, remove dead copper, pour order 1003): -0.508,-19.177 26.416,-19.177 26.416,-50.038 26.162,-50.292 25.019,-49.149 -1.016,-49.149
no net on Top Layer "Bottom Layer-No Net" (solid, remove dead copper, pour order 1002): -25.527,-19.183 1.397,-19.183 1.397,-50.044 1.143,-50.298 0,-49.155 -26.035,-49.155
no net on Top Layer "Bottom Layer-No Net" (solid, remove dead copper, pour order 1001): -25.527,28.823 1.397,28.823 1.397,-2.038 1.143,-2.292 0,-1.149 -26.035,-1.149
GND on Top Layer "Bottom Layer-No Net" (solid, remove dead copper, pour order 1000): -0.508,28.829 26.416,28.829 26.416,-2.032 26.162,-2.286 25.019,-1.143 -1.016,-1.143
no net on Bottom Layer "Bottom Layer-No Net" (solid, remove dead copper, pour order 1011): -50.927,25.769 -23.622,25.769 -22.098,24.245 -22.098,-3.568 -52.324,-3.568 -53.721,-2.171
no net on Bottom Layer "Bottom Layer-No Net" (solid, remove dead copper, pour order 1010): -50.927,-22.231 -23.622,-22.231 -22.098,-23.755 -22.098,-51.568 -52.324,-51.568 -53.721,-50.171
no net on Bottom Layer "Bottom Layer-No Net" (solid, remove dead copper, pour order 1009): -0.889,-22.225 26.416,-22.225 27.94,-23.749 27.94,-51.562 -2.286,-51.562 -3.683,-50.165
no net on Bottom Layer "Bottom Layer-No Net" (solid, remove dead copper, pour order 1008): -25.908,-22.231 1.397,-22.231 2.921,-23.755 2.921,-51.568 -27.305,-51.568 -28.702,-50.171
no net on Bottom Layer "Bottom Layer-No Net" (solid, remove dead copper, pour order 1007): -25.908,25.775 1.397,25.775 2.921,24.251 2.921,-3.562 -27.305,-3.562 -28.702,-2.165
GND on Bottom Layer "Bottom Layer-No Net" (solid, remove dead copper, pour order 1006): -0.889,25.781 26.416,25.781 27.94,24.257 27.94,-3.556 -2.286,-3.556 -3.683,-2.159

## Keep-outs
Keep-Out Layer:
  lines w0.152: -27.305,-48.018 -50.038,-48.018 -50.038,-0.012 ; -27.305,-2.038 -26.162,-2.038 -26.162,-0.006 -25.019,-0.006 ; -27.305,-2.026 -27.305,-0.012 ; -27.305,-0.018 -50.038,-0.018 -50.038,47.988 ; -27.305,45.962 -26.162,45.962 -26.162,47.994 -25.019,47.994 ; -27.305,45.974 -27.305,47.988 -50.038,47.988 ; -2.286,-48.018 -25.019,-48.018 -25.019,-0.012 ; -2.286,-2.038 -1.143,-2.038 -1.143,-0.006 ; -2.286,-2.026 -2.286,-0.012 ; -2.286,45.968 -1.143,45.968 -1.143,48 0,48 ; -2.286,45.98 -2.286,47.994 -25.019,47.994 ; 22.733,-48.012 0,-48.012 ; 22.733,-2.032 23.876,-2.032 23.876,0 ; 22.733,-2.02 22.733,-0.006 ; 22.733,45.974 23.876,45.974 23.876,48.006 25.019,48.006 25.019,0 ; 22.733,45.986 22.733,48 0,48 ; -50.038,-48.012 -50.038,-51.054 25.019,-51.054 25.019,-48.006 ; -50.038,-48.012 -50.038,-0.012 ; -50.038,-48.012 -27.305,-48.012 -27.305,-45.98 -26.162,-45.98 -26.162,-48.012 ; -50.038,-0.012 -50.038,47.988 ; -50.038,-0.012 -27.305,-0.012 ; -50.038,-0.012 -27.305,-0.012 ; -27.305,-0.012 -27.305,2.02 -26.162,2.02 -26.162,-0.012 ; -26.162,-48.012 -25.019,-48.012 ; -26.162,-48.012 -25.019,-48.012 ; -26.162,-0.012 -25.019,-0.012 ; -26.162,-0.012 -25.019,-0.012 ; -25.019,-48.012 -25.019,-0.006 ; -25.019,-48.012 -25.019,-0.012 ; -25.019,-48.012 -2.286,-48.012 -2.286,-45.98 -1.143,-45.98 -1.143,-48.012 ; -25.019,-0.012 -25.019,47.994 ; -25.019,-0.012 -2.286,-0.012 ; -25.019,-0.012 -2.286,-0.012 ; -25.019,-0.012 -25.019,47.994 ; -25.019,-0.006 -25.019,47.994 ; -25.019,-0.006 -2.286,-0.006 -2.286,2.026 -1.143,2.026 -1.143,-0.006 ; -1.143,-48.012 0,-48.012 ; -1.143,-48.012 0,-48.012 ; -1.143,-0.006 0,-0.006 ; -1.143,-0.006 0,-0.006 ; -1.143,-0.006 0,-0.006 ; 0,-48.012 0,-0.006 ; 0,-48.012 0,-0.006 ; 0,-0.006 22.733,-0.006 ; 0,-0.006 0,-48.006 22.733,-48.006 22.733,-45.974 23.876,-45.974 23.876,-48.006 ; 0,-0.006 0,48 ; 0,-0.006 0,48 ; 0,-0.006 22.733,-0.006 ; 0,48 0,0 22.733,0 22.733,2.032 23.876,2.032 23.876,0 ; 23.876,-48.006 25.019,-48.006 ; 23.876,-48.006 25.019,-48.006 ; 23.876,0 25.019,0 ; 23.876,0 25.019,0 ; 23.876,0 25.019,0 ; 25.019,-48.006 25.019,0

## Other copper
Top Layer:
  rectangle: -49.708,23.051 -47.371,27.42
  rectangle: -49.708,10.656 -47.371,14.771
  rectangle: -49.657,21.07 -46.99,28.309
  rectangle: -49.708,-24.949 -47.371,-20.58
  rectangle: -49.708,-37.344 -47.371,-33.229
  rectangle: -49.657,-26.93 -46.99,-19.691
  rectangle: 0.33,-24.943 2.667,-20.574
  rectangle: 0.33,-37.338 2.667,-33.223
  rectangle: 0.381,-26.924 3.048,-19.685
  rectangle: -24.689,-24.949 -22.352,-20.58
  rectangle: -24.689,-37.344 -22.352,-33.229
  rectangle: -24.638,-26.93 -21.971,-19.691
  rectangle: -24.689,23.057 -22.352,27.426
  rectangle: -24.689,10.662 -22.352,14.777
  rectangle: -24.638,21.076 -21.971,28.315
  rectangle net GND: 0.381,21.082 3.048,28.321
  rectangle net VCC: 0.33,10.668 2.667,14.783
  rectangle net GND: 0.33,23.063 2.667,27.432
  pour cut-out: -37.719,20.308 -34.925,20.308 -34.925,17.514 -37.719,17.514
  pour cut-out: -37.719,-27.692 -34.925,-27.692 -34.925,-30.486 -37.719,-30.486
  pour cut-out: 12.319,-27.686 15.113,-27.686 15.113,-30.48 12.319,-30.48
  pour cut-out: -12.7,-27.692 -9.906,-27.692 -9.906,-30.486 -12.7,-30.486
  pour cut-out: -12.7,20.314 -9.906,20.314 -9.906,17.52 -12.7,17.52
  pour cut-out: 12.319,20.32 15.113,20.32 15.113,17.526 12.319,17.526

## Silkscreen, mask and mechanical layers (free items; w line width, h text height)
Top Overlay:
  lines w0.152: -42.342,-24.873 -44.323,-24.873 -44.323,-26.752 -40.361,-26.752 -40.361,-24.746 ; -42.342,23.127 -44.323,23.127 -44.323,21.248 -40.361,21.248 -40.361,23.254 ; -17.323,-24.873 -19.304,-24.873 -19.304,-26.752 -15.342,-26.752 -15.342,-24.746 ; -17.323,23.133 -19.304,23.133 -19.304,21.254 -15.342,21.254 -15.342,23.26 ; 7.696,-24.867 5.715,-24.867 5.715,-26.746 9.677,-26.746 9.677,-24.74 ; 7.696,23.139 5.715,23.139 5.715,21.26 9.677,21.26 9.677,23.266 ; -46.609,-27.489 -46.609,-24.898 -44.602,-24.898 -44.602,-27.463 -44.628,-27.489 -46.609,-27.489 ; -46.609,20.511 -46.609,23.102 -44.602,23.102 -44.602,20.537 -44.628,20.511 -46.609,20.511 ; -21.59,-27.489 -21.59,-24.898 -19.583,-24.898 -19.583,-27.463 -19.609,-27.489 -21.59,-27.489 ; -21.59,20.517 -21.59,23.108 -19.583,23.108 -19.583,20.543 -19.609,20.517 -21.59,20.517 ; 3.429,-27.483 3.429,-24.892 5.436,-24.892 5.436,-27.457 5.41,-27.483 3.429,-27.483 ; 3.429,20.523 5.41,20.523 5.436,20.549 5.436,23.114 3.429,23.114 3.429,20.523
  text "RFID CARD V1.1" at -48.387,16.752 h1.52 r90
  text "RFID CARD V1.1" at -23.368,16.758 h1.52 r90
  text "RFID CARD V1.1" at 1.651,16.764 h1.52 r90
  text "RFID CARD V1.1" at -48.387,-31.248 h1.52 r90
  text "RFID CARD V1.1" at -23.368,-31.248 h1.52 r90
  text "RFID CARD V1.1" at 1.651,-31.242 h1.52 r90
Top Solder:
  rectangle: -49.784,10.529 -47.244,14.847
  rectangle: -49.784,22.975 -47.244,27.547
  rectangle: -49.784,-37.471 -47.244,-33.153
  rectangle: -49.784,-25.025 -47.244,-20.453
  rectangle: 0.254,-37.465 2.794,-33.147
  rectangle: 0.254,-25.019 2.794,-20.447
  rectangle: -24.765,-37.471 -22.225,-33.153
  rectangle: -24.765,-25.025 -22.225,-20.453
  rectangle: -24.765,10.535 -22.225,14.853
  rectangle: -24.765,22.981 -22.225,27.553
  rectangle: 0.254,22.987 2.794,27.559
  rectangle: 0.254,10.541 2.794,14.859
